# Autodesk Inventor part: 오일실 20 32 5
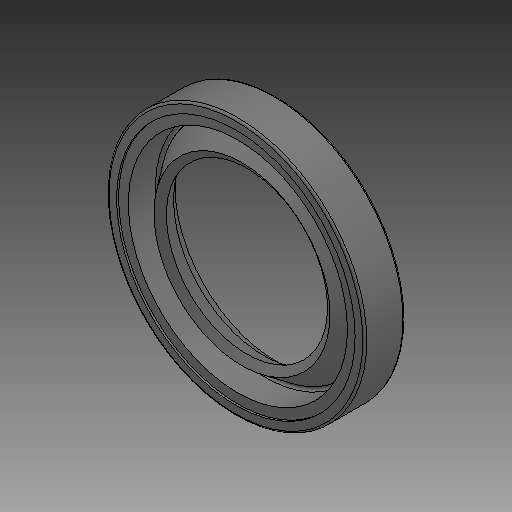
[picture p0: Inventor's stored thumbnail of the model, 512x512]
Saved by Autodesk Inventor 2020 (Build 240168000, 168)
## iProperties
Created: 2024-08
Part Number: 오일실 20 32 5
Material: 고무
Description: 오일 실 - 비스프링, 조립 GA
Document SubType Name: Modeling
Designer: 1강의실14
Density: 0.93 g/cm^3
Appearance: 기본값
Author: jhkim
Sending System: Autodesk Inventor 2025
Preprocessor: ST-DEVELOPER v20
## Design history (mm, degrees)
feature "Solid1"
node "솔리드1"
